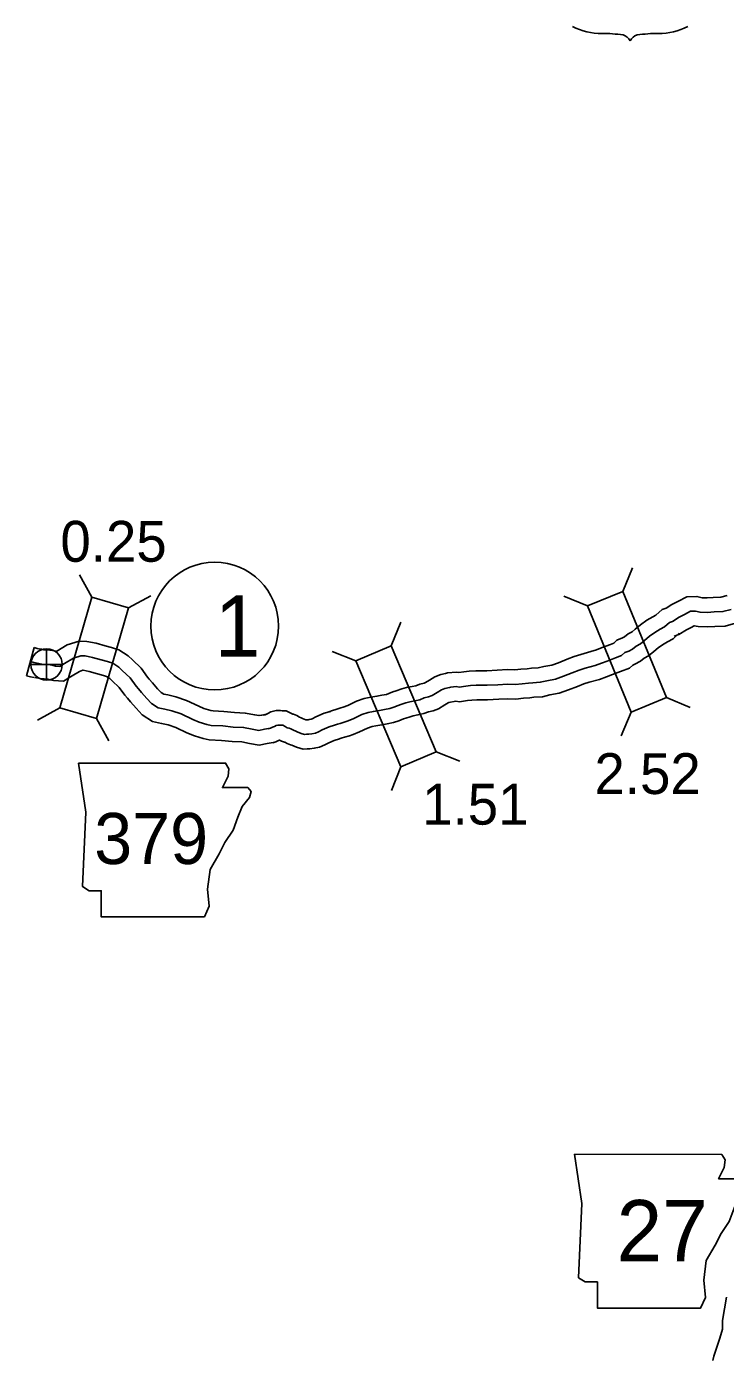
# Model space of a CAD drawing. Extents: x -83719 to 153526, y -11835 to 11446.
# Drawn here: x -4825.1 to -4584.3, y -3452.7 to -2993.1 of the extents above; entities that cross this region are included whole.
import ezdxf

# ---------------------------------------------------------------- set-up
doc = ezdxf.new("R2010")
doc.units = 0
for name, color, linetype in [('Level 10', 7, 'Continuous'), ('Level 20', 7, 'Continuous'), ('Level 21', 7, 'Continuous'), ('Level 22', 7, 'Continuous'), ('Level 26', 7, 'Continuous'), ('Level 27', 7, 'Continuous'), ('Level 58', 7, 'Continuous'), ('Level 59', 7, 'Continuous')]:
    doc.layers.add(name, color=color, linetype=linetype)

msp = doc.modelspace()

# ---------------------------------------------------------------- linework, layer by layer
at = {"layer": 'Level 10'}
for points in [[(-4583.69, -3189.12), (-4585.84, -3189.7), (-4588.43, -3189.78), (-4590.6, -3189.96), (-4592.31, -3189.9), (-4594.06, -3189.48), (-4597.54, -3189.59), (-4600.7, -3191.23), (-4602.68, -3192.25), (-4604.65, -3193.5), (-4606.06, -3193.98)], [(-4606.06, -3193.98), (-4608.21, -3195.88), (-4609.23, -3196.47), (-4611.31, -3197.67), (-4613.53, -3199.25), (-4615.36, -3200.78), (-4616.36, -3201.61), (-4617.8, -3202.4), (-4619.08, -3203.4), (-4619.73, -3203.76), (-4621.66, -3204.55), (-4622.72, -3205.54), (-4623.89, -3205.98)], [(-4600.2, -3202.14), (-4602.32, -3204.02), (-4604.22, -3205.13), (-4605.91, -3206.1), (-4607.4, -3207.16), (-4608.95, -3208.46), (-4610.73, -3209.93), (-4612.27, -3210.78), (-4613.58, -3211.8), (-4615.44, -3212.81), (-4616.17, -3213.11), (-4617.35, -3214.21), (-4620.37, -3215.34)], [(-4580.82, -3198.71), (-4584.38, -3199.66), (-4587.86, -3199.77), (-4590.35, -3199.97), (-4593.64, -3199.87), (-4595, -3199.54), (-4596.11, -3200.12), (-4597.7, -3200.94), (-4600.31, -3202.6), (-4601.93, -3203.14)], [(-4822.57, -3207.1), (-4825.12, -3216.77)], [(-4820.47, -3207.6), (-4821.47, -3207.39), (-4822.57, -3207.1)], [(-4782.84, -3218), (-4783.47, -3217.27), (-4785.67, -3214.22), (-4788.67, -3211.35), (-4790.16, -3209.89), (-4793.33, -3207.85), (-4795.93, -3207.07), (-4798.06, -3206.52), (-4801.19, -3205.61), (-4804.39, -3204.95), (-4807.07, -3204.85), (-4811.12, -3206.12), (-4814.68, -3208.32), (-4814.83, -3208.42), (-4815.05, -3208.37), (-4816.21, -3208.15), (-4818.01, -3207.89), (-4819.22, -3207.81), (-4820.04, -3207.66), (-4820.7, -3207.55)], [(-4623.88, -3205.98), (-4626.79, -3207.06), (-4628.7, -3207.83), (-4630.63, -3208.49), (-4634.06, -3209.44), (-4636.34, -3210.17), (-4638.86, -3211.12), (-4641.82, -3212.3), (-4644.13, -3213.1), (-4646.86, -3213.62), (-4648.81, -3214.1), (-4651.06, -3214.24), (-4652.59, -3214.39), (-4654.77, -3214.58), (-4656.88, -3214.81), (-4659.37, -3214.7), (-4662.91, -3214.92), (-4666.48, -3215.08), (-4670.32, -3215.05), (-4672.62, -3215.22), (-4674.39, -3215.43), (-4676.16, -3215.68)], [(-4821.48, -3212.49), (-4822.61, -3212.26), (-4823.84, -3211.94)], [(-4822.48, -3217.39), (-4823.75, -3217.13), (-4825.12, -3216.77)], [(-4790.41, -3224.53), (-4791.32, -3223.47), (-4793.24, -3220.82), (-4795.63, -3218.53), (-4796.43, -3217.75), (-4797.55, -3217.03), (-4798.62, -3216.71), (-4800.71, -3216.16), (-4803.6, -3215.33), (-4805.6, -3214.91), (-4805.72, -3214.9), (-4806.93, -3215.28), (-4809.4, -3216.81), (-4812.42, -3218.7), (-4815.86, -3218.42), (-4817.02, -3218.18), (-4817.86, -3218.02), (-4819.07, -3217.84), (-4820.46, -3217.75), (-4821.71, -3217.52), (-4822.25, -3217.43)], [(-4676.16, -3215.63), (-4676.93, -3215.52), (-4680.06, -3215.78), (-4680.71, -3216.04), (-4682.41, -3216.33), (-4684.48, -3217.22), (-4686.21, -3218.29), (-4687.59, -3219.13), (-4688.07, -3219.31), (-4689.54, -3219.69), (-4691, -3220.23), (-4692.27, -3220.5), (-4694.2, -3220.88), (-4695.84, -3221.34), (-4697.73, -3221.96), (-4698.87, -3222.37), (-4700.27, -3222.97), (-4701.09, -3223.23), (-4702.69, -3223.53), (-4704.37, -3223.86), (-4706.47, -3224.15), (-4708.73, -3224.63), (-4711.44, -3225.55), (-4714.41, -3227.01), (-4715.97, -3227.63), (-4716.81, -3227.9), (-4718.6, -3228.42), (-4719.66, -3228.78), (-4720.98, -3229.25), (-4720.99, -3229.25)], [(-4620.39, -3215.35), (-4623.19, -3216.39), (-4625.2, -3217.2), (-4627.66, -3218.05), (-4631.21, -3219.03), (-4633.05, -3219.62), (-4635.25, -3220.45), (-4638.33, -3221.67), (-4641.54, -3222.79), (-4644.73, -3223.39), (-4647.3, -3224.03), (-4650.25, -3224.21), (-4651.65, -3224.35), (-4653.81, -3224.54), (-4656.56, -3224.83), (-4659.27, -3224.71), (-4662.39, -3224.9), (-4666.29, -3225.08), (-4669.98, -3225.05), (-4671.67, -3225.18), (-4673.11, -3225.34), (-4675.97, -3225.76)], [(-4742, -3229.95), (-4744.1, -3230.34), (-4745.08, -3230.53), (-4746.48, -3230.28), (-4749.75, -3229.64), (-4753.53, -3229.5), (-4757.14, -3229.11), (-4760.81, -3228.93), (-4761.68, -3228.72), (-4763.99, -3228.05), (-4765.81, -3227.29), (-4770, -3225.28), (-4773.67, -3224.07), (-4776.45, -3223.43), (-4777.86, -3223.14), (-4778.8, -3222.53), (-4779.98, -3221.25), (-4781.78, -3219.23), (-4782.84, -3218)], [(-4740.18, -3239.78), (-4742.27, -3240.17), (-4745.02, -3240.69), (-4748.3, -3240.11), (-4750.9, -3239.61), (-4754.26, -3239.48), (-4757.92, -3239.08), (-4762.26, -3238.87), (-4764.26, -3238.38), (-4767.3, -3237.5), (-4769.89, -3236.43), (-4773.75, -3234.58), (-4776.36, -3233.71), (-4778.6, -3233.2), (-4781.72, -3232.54), (-4785.28, -3230.25), (-4787.4, -3227.96), (-4789.31, -3225.81), (-4790.41, -3224.53)], [(-4675.97, -3225.76), (-4677.22, -3225.58), (-4679.54, -3225.98), (-4679.86, -3226.12), (-4680.98, -3226.81), (-4683.18, -3228.15), (-4685.03, -3228.86), (-4686.55, -3229.24), (-4688.21, -3229.86), (-4690.27, -3230.3), (-4691.87, -3230.62), (-4692.95, -3230.92), (-4694.45, -3231.41), (-4695.18, -3231.67), (-4696.82, -3232.37), (-4698.67, -3232.95), (-4700.8, -3233.35), (-4702.71, -3233.72), (-4704.73, -3234), (-4706.07, -3234.29), (-4707.62, -3234.82), (-4710.36, -3236.16), (-4712.58, -3237.04), (-4713.86, -3237.46), (-4715.61, -3237.97), (-4716.4, -3238.23), (-4717.01, -3238.45), (-4717.24, -3238.57)], [(-4720.42, -3229.06), (-4722.54, -3229.69), (-4725.44, -3230.91), (-4726.71, -3231.64), (-4727.03, -3231.77), (-4727.72, -3231.9), (-4728.11, -3231.96), (-4728.81, -3231.94), (-4728.87, -3231.95), (-4730, -3231.48), (-4730.53, -3231.27), (-4731.04, -3231.06), (-4732, -3230.54), (-4733.19, -3230.09), (-4733.37, -3230.05), (-4733.59, -3229.91), (-4735.69, -3228.85), (-4737.07, -3228.86), (-4737.6, -3228.8), (-4739.1, -3228.81), (-4740.93, -3229.22), (-4741.97, -3229.78), (-4742.45, -3230), (-4742.91, -3230.21), (-4743.52, -3230.42)], [(-4717.27, -3238.55), (-4719.17, -3239.12), (-4720.99, -3239.88), (-4722.31, -3240.64), (-4724.17, -3241.4), (-4726.01, -3241.76), (-4727.49, -3241.99), (-4728.46, -3241.96), (-4729.83, -3242.1), (-4732.14, -3241.42), (-4733.75, -3240.75), (-4734.22, -3240.56), (-4735.32, -3240.12), (-4736.17, -3239.66), (-4736.19, -3239.65), (-4737.27, -3239.37), (-4737.97, -3238.95), (-4738.33, -3239.12), (-4739.26, -3239.53), (-4740.26, -3239.87)], [(-4583.93, -3430.94), (-4585.24, -3439.02), (-4585.3, -3441.94), (-4586.19, -3445.1), (-4587.5, -3448.86), (-4588.23, -3451.23), (-4588.63, -3452.71)]]:
    msp.add_lwpolyline(points, dxfattribs=at)
at = {"layer": 'Level 20'}
for p, q in [((-4619.64, -3187.71), (-4616.26, -3179.59)), ((-4802.69, -3189.77), (-4806.93, -3182.06)), ((-4790.01, -3193.44), (-4782.3, -3189.2)), ((-4631.85, -3192.74), (-4639.97, -3189.36)), ((-4699.45, -3206.54), (-4696.16, -3198.38)), ((-4711.6, -3211.71), (-4719.76, -3208.41)), ((-4604.56, -3224.33), (-4596.44, -3227.71)), ((-4813.71, -3227.81), (-4821.41, -3232.05)), ((-4616.77, -3229.36), (-4620.15, -3237.48)), ((-4801.03, -3231.48), (-4796.78, -3239.19)), ((-4683.96, -3242.99), (-4675.8, -3246.28)), ((-4696.11, -3248.15), (-4699.4, -3256.31))]:
    msp.add_line(p, q, dxfattribs=at)
for points in [[(-4604.56, -3224.33), (-4619.64, -3187.71), (-4631.85, -3192.74), (-4616.77, -3229.36)], [(-4801.03, -3231.48), (-4790.01, -3193.44), (-4802.69, -3189.77), (-4813.71, -3227.81)], [(-4683.96, -3242.99), (-4699.45, -3206.54), (-4711.6, -3211.71), (-4696.11, -3248.15)]]:
    msp.add_lwpolyline(points, close=True, dxfattribs=at)
at = {"layer": 'Level 21'}
for points in [[(-4807.28, -3246.88), (-4804.74, -3263.79), (-4805.87, -3289.45), (-4803.61, -3290.86), (-4799.38, -3290.86), (-4799.38, -3299.88), (-4763.86, -3299.88), (-4762.17, -3296.22), (-4762.73, -3290.3), (-4761.88, -3283.53), (-4758.78, -3278.17), (-4756.81, -3274.23), (-4753.99, -3270), (-4752.3, -3265.48), (-4750.89, -3261.82), (-4748.35, -3258.72), (-4747.78, -3256.74), (-4748.91, -3255.33), (-4757.65, -3255.33), (-4755.68, -3251.39), (-4755.4, -3248.85), (-4756.57, -3246.9)], [(-4636.26, -3381.7), (-4633.72, -3398.61), (-4634.85, -3424.27), (-4632.59, -3425.68), (-4628.36, -3425.68), (-4628.36, -3434.71), (-4592.83, -3434.71), (-4591.14, -3431.04), (-4591.71, -3425.12), (-4590.86, -3418.35), (-4587.76, -3413), (-4585.78, -3409.05), (-4582.97, -3404.82), (-4581.27, -3400.31), (-4579.86, -3396.64), (-4577.33, -3393.54), (-4576.76, -3391.57), (-4577.89, -3390.16), (-4586.63, -3390.16), (-4584.66, -3386.21), (-4584.38, -3383.67), (-4585.54, -3381.72)]]:
    msp.add_lwpolyline(points, close=True, dxfattribs=at)
at = {"layer": 'Level 22'}
for centre, radius, start, end in [((-4626.69, -2971.95), 23.53, 244.0771, 269.5779), ((-4626.15, -3038.59), 43.11, 81.1942, 90.9539), ((-4620.76, -2999.94), 4.13, 28.0342, 72.9864), ((-4613.47, -2999.94), 4.13, 107.0136, 151.9658), ((-4608.08, -3038.59), 43.11, 89.0461, 98.8058), ((-4607.53, -2971.95), 23.53, 270.4221, 295.9229)]:
    msp.add_arc(centre, radius, start, end, dxfattribs=at)
at = {"layer": 'Level 26'}
for p, q in [((-4818.25, -3218.34), (-4818.25, -3207.5)), ((-4823.67, -3212.92), (-4812.83, -3212.92))]:
    msp.add_line(p, q, dxfattribs=at)
msp.add_circle((-4818.25, -3212.92), 5.42, dxfattribs=at)
at = {"layer": 'Level 27'}
msp.add_circle((-4760.28, -3199.69), 22, dxfattribs=at)
at = {"layer": 'Level 59'}
for points in [[(-4582.25, -3193.91), (-4585.11, -3194.68), (-4588.14, -3194.77), (-4590.48, -3194.96), (-4592.98, -3194.89), (-4594.58, -3194.5), (-4596.25, -3194.55), (-4598.4, -3195.67), (-4600.19, -3196.59), (-4602.48, -3198.05), (-4603.51, -3198.4)], [(-4603.51, -3198.4), (-4605.26, -3199.95), (-4606.72, -3200.8), (-4608.61, -3201.88), (-4610.47, -3203.2), (-4612.15, -3204.62), (-4613.54, -3205.77), (-4615.04, -3206.59), (-4616.33, -3207.6), (-4617.59, -3208.28), (-4618.92, -3208.83), (-4620.04, -3209.87), (-4622.13, -3210.66)], [(-4786.62, -3221.27), (-4787.4, -3220.37), (-4789.46, -3217.52), (-4792.15, -3214.94), (-4793.29, -3213.82), (-4795.44, -3212.44), (-4797.28, -3211.89), (-4799.38, -3211.34), (-4802.39, -3210.47), (-4805, -3209.93), (-4806.4, -3209.88), (-4809.02, -3210.7), (-4812.04, -3212.57), (-4813.66, -3213.59), (-4815.13, -3213.47), (-4816.03, -3213.28), (-4817.04, -3213.08), (-4818.54, -3212.87), (-4819.84, -3212.78), (-4820.87, -3212.59), (-4821.48, -3212.49)], [(-4622.13, -3210.66), (-4624.99, -3211.73), (-4626.95, -3212.51), (-4629.14, -3213.27), (-4632.63, -3214.24), (-4634.69, -3214.89), (-4637.05, -3215.78), (-4640.08, -3216.98), (-4642.83, -3217.94), (-4645.8, -3218.51), (-4648.06, -3219.06), (-4650.66, -3219.22), (-4652.12, -3219.37), (-4654.29, -3219.56), (-4656.72, -3219.82), (-4659.32, -3219.71), (-4662.65, -3219.91), (-4666.38, -3220.08), (-4670.15, -3220.05), (-4672.15, -3220.2), (-4673.75, -3220.38), (-4675.98, -3220.71)], [(-4741.09, -3234.87), (-4743.18, -3235.26), (-4745.05, -3235.61), (-4747.39, -3235.2), (-4750.33, -3234.63), (-4753.89, -3234.49), (-4757.53, -3234.1), (-4761.53, -3233.9), (-4762.97, -3233.55), (-4765.64, -3232.77), (-4767.85, -3231.86), (-4771.87, -3229.93), (-4775.02, -3228.89), (-4777.52, -3228.32), (-4779.79, -3227.84), (-4782.04, -3226.39), (-4783.69, -3224.61), (-4785.54, -3222.52), (-4786.62, -3221.27)], [(-4675.98, -3220.71), (-4677.08, -3220.55), (-4678.91, -3220.7), (-4679.34, -3220.87), (-4680.98, -3221.16), (-4682.17, -3221.67), (-4683.6, -3222.55), (-4685.39, -3223.64), (-4686.55, -3224.08), (-4688.05, -3224.46), (-4689.61, -3225.05), (-4691.27, -3225.4), (-4693.03, -3225.75), (-4694.4, -3226.13), (-4696.09, -3226.68), (-4697.02, -3227.02), (-4698.55, -3227.67), (-4699.88, -3228.09), (-4701.74, -3228.44), (-4703.54, -3228.79), (-4705.6, -3229.08), (-4707.4, -3229.46), (-4709.53, -3230.18), (-4712.38, -3231.58), (-4714.28, -3232.33), (-4715.34, -3232.68), (-4717.1, -3233.2), (-4718.03, -3233.51), (-4718.99, -3233.85), (-4718.99, -3233.85)], [(-4718.99, -3233.85), (-4720.86, -3234.4), (-4723.21, -3235.39), (-4724.51, -3236.14), (-4725.6, -3236.58), (-4726.87, -3236.83), (-4727.8, -3236.97), (-4728.63, -3236.95), (-4729.37, -3237.02), (-4730.47, -3236.7), (-4731.88, -3236.11), (-4732.38, -3235.92), (-4733.18, -3235.59), (-4734.09, -3235.1), (-4734.69, -3234.87), (-4735.32, -3234.71), (-4736.03, -3234.28), (-4736.86, -3233.86), (-4737.33, -3233.86), (-4737.86, -3233.8), (-4738.53, -3233.81), (-4739.16, -3233.95), (-4739.73, -3234.25), (-4740.39, -3234.56), (-4741.09, -3234.87), (-4741.89, -3235.14)]]:
    msp.add_lwpolyline(points, dxfattribs=at)

# ---------------------------------------------------------------- texts
at = {"layer": 'Level 21'}
for s, height, p in [('379', 17.6, (-4801.84, -3281.67)), ('27', 21.12, (-4621.75, -3418.59))]:
    msp.add_text(s, height=height, dxfattribs=at).set_placement(p)
at = {"layer": 'Level 27'}
msp.add_text('1', height=21.12, dxfattribs=at).set_placement((-4760.28, -3210.25))
at = {"layer": 'Level 58'}
for s, p in [('0.25', (-4813.49, -3177.51)), ('2.52', (-4629.4, -3257.56)), ('1.51', (-4688.78, -3268.1))]:
    msp.add_text(s, height=14.08, dxfattribs=at).set_placement(p)

doc.saveas('drawing.dxf')
